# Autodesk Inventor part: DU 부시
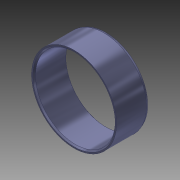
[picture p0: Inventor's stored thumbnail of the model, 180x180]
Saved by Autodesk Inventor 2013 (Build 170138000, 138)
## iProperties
Created: 2023-11
Part Number: DU 부시
Material: 강철, 합금
Document SubType Name: Modeling
Designer: mdu-01
Density: 1 g/cm^3
Author: mdu-01
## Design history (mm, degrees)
sketch "스케치1"
  geometry: L1 (0, 0)-(0, -30); L2 (38.75, 0)-(40, 0); L3 (40, 0)-(40, -28.125); L4 (39.318, -30)-(37.75, -30); L5 (37.5, -29.75)-(37.5, -1.25); L6 (38.75, 0)-(37.5, -1.25); L7 (40, -28.125)-(39.318, -30); L8 (37.75, -30)-(37.5, -29.75); 3 further points
  constraints: 16 end point, 8 point on line, 2 parallel, 1 horizontal, 1 perpendicular, 1 vertical
  dimensions: "d0" = 30 distance of L1.start L1.end; "d1" = 1.25 distance of L2.start point (37.5, 0); "d2" = 1.25 distance of L5.end point (37.5, 0) (= d1); "d3" = 1.875 distance of L3.end point (40, -30); "d4" = 20 deg angle of L3 L7; "d5" = 0.25 distance of L4.end point (37.5, -30); "d6" = 0.25 distance of L5.start point (37.5, -30) (= d5); "d7" = 75 diameter of L5 L1; "d8" = 80 diameter of L3 L1
revolve "회전1" sketch "스케치1" stored, may be unused: angle "d9" = 90 deg
node "솔리드1"
